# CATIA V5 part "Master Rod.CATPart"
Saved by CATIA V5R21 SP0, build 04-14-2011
Part number: Master Rod
Bounding box of the stored display mesh (mm): x -55.99 to 55.99, y -51.999 to 267.322, z -35 to 35
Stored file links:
  D:\CATIA V5R21 E-RESOURCES\CATIA-V5R21\catia-v5r21-Prts\c12_catia_v5r21_prt\c12_catia_v5r21figr_12-26\Master Rod.CATPart
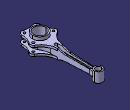
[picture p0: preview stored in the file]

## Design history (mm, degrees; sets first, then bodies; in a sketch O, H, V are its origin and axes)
Body1 (main body)
  Sketch1 on xy-plane, origin (0, 0, 0), H (1, 0, 0), V (0, 1, 0)
    arc A1 centre (0, 0) radius 31.5 from (-26.3425, 17.272) to (26.3425, 17.272) ccw
    arc A2 centre (0, 250) radius 17.5 from (14.7398, 240.5666) to (-14.7398, 240.5666) ccw
    point P1 (0, 250)
    line L1 (9, 220) -> (13, 60)
    point P2 (9, 220)
    point P3 (13, 60)
    arc A3 centre (94.6219, 62.0405) radius 81.6474 from (13, 60) to (26.3425, 17.272) ccw
    point P5 (26.3425, 17.272)
    arc A4 centre (45.4514, 220.9113) radius 36.4628 from (9, 220) to (14.7398, 240.5666) cw
    point P7 (14.7398, 240.5666)
    point P8 (-14.7398, 240.5666)
    point P9 (-9, 220)
    arc A5 centre (-45.4514, 220.9113) radius 36.4628 from (-9, 220) to (-14.7398, 240.5666) ccw
    point P11 (-13, 60)
    line L2 (-9, 220) -> (-13, 60)
    point P12 (-26.3425, 17.272)
    arc A6 centre (-94.6219, 62.0405) radius 81.6474 from (-13, 60) to (-26.3425, 17.272) cw
    radius A1 = 31.5
    radius A2 = 17.5
    distance P1 H = 250
    distance V P3 = 13
    distance P2 V = 9
    distance P1 P2 V = 30
    distance P3 P2 V = 160
    coincidence: P1 V
    tangency: A3 L1, A3 A1, A4 L1, A4 A2
    symmetry: P7 P8 V, P2 P9 V, A4 A5 V, P3 P11 V, L1 L2 V, P5 P12 V, A3 A6 V
  Pad1: profile Sketch1, direction (0, 0, 1), length 21, mirrored extent
  Sketch2 on face of Pad1, origin (0, 0, 21), H (1, 0, 0), V (0, 1, 0)
    point P1 (43, 16)
    point P2 (26, -39)
    arc A1 centre (43, 16) radius 13 from (53.3864, 8.1819) to (49.3111, 27.3653) ccw
    arc A2 centre (26, -39) radius 13 from (22.0235, -51.3769) to (38.9864, -38.4063) ccw
    reference projected line E1 (9, 220) -> (12.2872, 88.5122) from edge of Pad1
    arc A3 centre (84.2647, 90.3117) radius 72 from (49.3111, 27.3653) to (12.2872, 88.5122) cw
    point P5 (49.3111, 27.3653)
    point P6 (12.2872, 88.5122)
    arc A4 centre (110.9113, -35.118) radius 72 from (38.9864, -38.4063) to (53.3864, 8.1819) cw
    point P8 (38.9864, -38.4063)
    point P9 (53.3864, 8.1819)
    point P10 (-12.2872, 88.5122)
    point P11 (-49.3111, 27.3653)
    arc A5 centre (-84.2647, 90.3117) radius 72 from (-49.3111, 27.3653) to (-12.2872, 88.5122) ccw
    point P13 (-53.3864, 8.1819)
    arc A6 centre (-43, 16) radius 13 from (-53.3864, 8.1819) to (-49.3111, 27.3653) cw
    point P15 (-38.9864, -38.4063)
    arc A7 centre (-110.9113, -35.118) radius 72 from (-38.9864, -38.4063) to (-53.3864, 8.1819) ccw
    arc A8 centre (-26, -39) radius 13 from (-22.0235, -51.3769) to (-38.9864, -38.4063) cw
    line L1 (12.2872, 88.5122) -> (-12.2872, 88.5122)
    arc A9 centre (0, -119.9259) radius 72 from (-22.0235, -51.3769) to (22.0235, -51.3769) cw
    distance V P2 = 26
    distance P2 P1 H = 17
    distance P1 P2 V = 55
    distance P2 H = 39
    radius A1 = 13
    radius A2 = 13
    radius A3 = 72
    radius A4 = 72
    radius A9 = 72
    tangency: A3 E1, A3 A1, A4 A1, A4 A2, A9 A8, A9 A2
    symmetry: P6 P10 V, P5 P11 V, A3 A5 V, P9 P13 V, A1 A6 V, P8 P15 V, A4 A7 V, A2 A8 V
    horizontal: L1 H
  Pad2: profile Sketch2, direction (0, 0, -1), length 9
  Mirror1: of Pad2, Sketch2, about xy-plane
  Sketch3 on xy-plane, origin (0, 0, 0), H (1, 0, 0), V (0, 1, 0)
    circle A1 centre (0, 0) radius 31.5
    reference projected arc E1 centre (0, 0) radius 31.5 from (-26.3425, 17.272) to (26.3425, 17.272) ccw from edge of Pad2
    tangency: A1 E1
  Pad3: profile Sketch3, direction (0, 0, 1), length 35, mirrored extent
  Sketch4 on xy-plane, origin (0, 0, 0), H (1, 0, 0), V (0, 1, 0)
    circle A1 centre (0, 0) radius 26
    circle A2 centre (43, 16) radius 5
    circle A3 centre (26, -39) radius 5
    reference projected arc E1 centre (43, 16) radius 13 from (53.3864, 8.1819) to (49.3111, 27.3653) ccw from edge of Pad2
    reference projected arc E2 centre (26, -39) radius 13 from (22.0235, -51.3769) to (38.9864, -38.4063) ccw from edge of Pad2
    circle A4 centre (-26, -39) radius 5
    circle A5 centre (-43, 16) radius 5
    radius A1 = 26
    radius A3 = 5
    radius A2 = 5
    concentricity: A2 E1, A3 E2
    symmetry: A3 A4 V, A2 A5 V
  Pocket1: profile Sketch4, direction (0, 0, -1), length 35, mirrored extent
  Sketch5 on yz-plane, origin (0, 0, 0), H (0, 1, 0), V (0, 0, 1)
    line L1 (123.0834, 12) -> (250, 9)
    point P1 (123.0834, 12)
    point P2 (250, 9)
    arc A1 centre (124.9266, 89.9782) radius 78 from (88.5122, 21) to (123.0834, 12) ccw
    line L2 (88.5122, 21) -> (88.5122, 33.8539)
    line L3 (88.5122, 33.8539) -> (280.7471, 33.8539)
    line L4 (280.7471, 33.8539) -> (280.7471, 8.2732)
    point P8 (280.7471, 8.2732)
    line L5 (280.7471, 8.2732) -> (250, 9)
    distance P1 H = 12
    distance H P2 = 9
    distance V P2 = 250
    radius A1 = 78
    tangency: A1 L1, L5 A1
    vertical: L2 V, L4 V
    horizontal: L3 H
    coincidence: P8 L1
  Pocket2: profile Sketch5, direction (-1, 0, 0), length 35, mirrored extent
  Mirror2: of Pocket2, Sketch5, about xy-plane
  Sketch6 on xy-plane, origin (0, 0, 0), H (1, 0, 0), V (0, 1, 0)
    circle A1 centre (0, 250) radius 17.5
    point P1 (0, 250)
    reference projected arc E1 centre (0, 250) radius 17.5 from (17.5, 250) to (-17.5, 250) ccw from edge of Mirror2
    reference projected arc E2 centre (0, 250) radius 17.5 from (17.5, 250) to (-17.5, 250) ccw from edge of Mirror2
    coincidence: P1 V
    concentricity: E1 A1
    tangency: E2 A1
  Pad4: profile Sketch6, direction (0, 0, 1), length 21, mirrored extent
  Sketch7 on xy-plane, origin (0, 0, 0), H (1, 0, 0), V (0, 1, 0)
    circle A1 centre (0, 250) radius 12
    point P1 (0, 250)
    reference projected circle E1 centre (0, 250) radius 17.5 from edge of Pad4
    radius A1 = 12
    coincidence: P1 V
    concentricity: A1 E1
  Pocket3: profile Sketch7, direction (0, 0, -1), length 21, mirrored extent
  Sketch8 on xy-plane, origin (0, 0, 0), H (1, 0, 0), V (0, 1, 0)
    construction line L1 (0, 70) -> (0, 220)
    point P1 (0, 70)
    point P2 (0, 220)
    line L2 (-6, 70) -> (-6, 220)
    line L3 (6, 220) -> (6, 70)
    arc A1 centre (0, 220) radius 6 from (-6, 220) to (6, 220) cw
    arc A2 centre (0, 70) radius 6 from (6, 70) to (-6, 70) cw
    point P7 (0, 250)
    reference projected circle E1 centre (0, 250) radius 12 from edge of Pocket3
    length L1 = 150
    distance P7 P2 = 30
    radius A1 = 6
    coincidence: P1 V, P7 L1
    vertical: L1 V
    tangency: A1 L2, A2 L2, A1 L3, A2 L3
    parallelism: L1 L2
    concentricity: P7 E1
  Pocket4: profile Sketch8, direction (0, 0, 1), through (limit type 6), opposite side length -2.5
  Mirror3: of Pocket4, Sketch8, about xy-plane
